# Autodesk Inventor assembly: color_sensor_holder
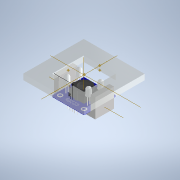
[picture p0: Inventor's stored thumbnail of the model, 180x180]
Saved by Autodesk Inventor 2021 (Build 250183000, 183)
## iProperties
Created: 2026-10
Part Number: color_sensor_holder
Document SubType Name: Assembly
Designer: alolo
Author: alolo
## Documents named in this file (5)
- C:\Users\alolo\Documents\Inventor\Design 1\color_sensor_holder.iam
- C:\Users\alolo\Documents\Inventor\Design 1\color_sensor_holder_base.ipt
- C:\Users\alolo\Documents\Inventor\Design 1\TCS3200 Color Sensor Module.ipt
- C:\Users\alolo\Documents\Inventor\Design 1\color_sensor_holer_side.ipt
- C:\Users\alolo\Documents\Inventor\Design 1\color_sensor_holder_top.ipt
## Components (5 placed, 4 different names)
1. color_sensor_holder_base:1 — Mate:1, Mate:15, Mate:16, Mate:17, Mate:18, Mate:19, Mate:21, Mate:22, Mate:23, Mate:24, Mate:25, Mate:31, Mate:37, Mate:38
2. TCS3200 Color Sensor Module:1 — Mate:1, Mate:13, Mate:33, Mate:34, Mate:35, Mate:36
3. color_sensor_holer_side:1 — Mate:31, Mate:39, Mate:44
4. color_sensor_holer_side:2 — Mate:15, Mate:40, Mate:43, Mate:54
5. color_sensor_holder_top:1 — Mate:43, Mate:44, Mate:45, Mate:46, Mate:47, Mate:48, Mate:49, Mate:54
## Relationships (29: Mate 29)
- Mate:1: color_sensor_holder_base:1 ↔ TCS3200 Color Sensor Module:1
- Mate:13: TCS3200 Color Sensor Module:1
- Mate:15: color_sensor_holder_base:1 ↔ color_sensor_holer_side:2
- Mate:16: color_sensor_holder_base:1
- Mate:17: color_sensor_holder_base:1
- Mate:18: color_sensor_holder_base:1
- Mate:19: color_sensor_holder_base:1
- Mate:21: color_sensor_holder_base:1
- Mate:22: color_sensor_holder_base:1
- Mate:23: color_sensor_holder_base:1
- Mate:24: color_sensor_holder_base:1
- Mate:25: color_sensor_holder_base:1
- Mate:31: color_sensor_holder_base:1 ↔ color_sensor_holer_side:1
- Mate:33: TCS3200 Color Sensor Module:1
- Mate:34: TCS3200 Color Sensor Module:1
- Mate:35: TCS3200 Color Sensor Module:1
- Mate:36: TCS3200 Color Sensor Module:1
- Mate:37: color_sensor_holder_base:1
- Mate:38: color_sensor_holder_base:1
- Mate:39: color_sensor_holer_side:1
- Mate:40: color_sensor_holer_side:2
- Mate:43: color_sensor_holer_side:2 ↔ color_sensor_holder_top:1
- Mate:44: color_sensor_holer_side:1 ↔ color_sensor_holder_top:1
- Mate:45: color_sensor_holder_top:1
- Mate:46: color_sensor_holder_top:1
- Mate:47: color_sensor_holder_top:1
- Mate:48: color_sensor_holder_top:1
- Mate:49: color_sensor_holder_top:1
- Mate:54: color_sensor_holer_side:2 ↔ color_sensor_holder_top:1
